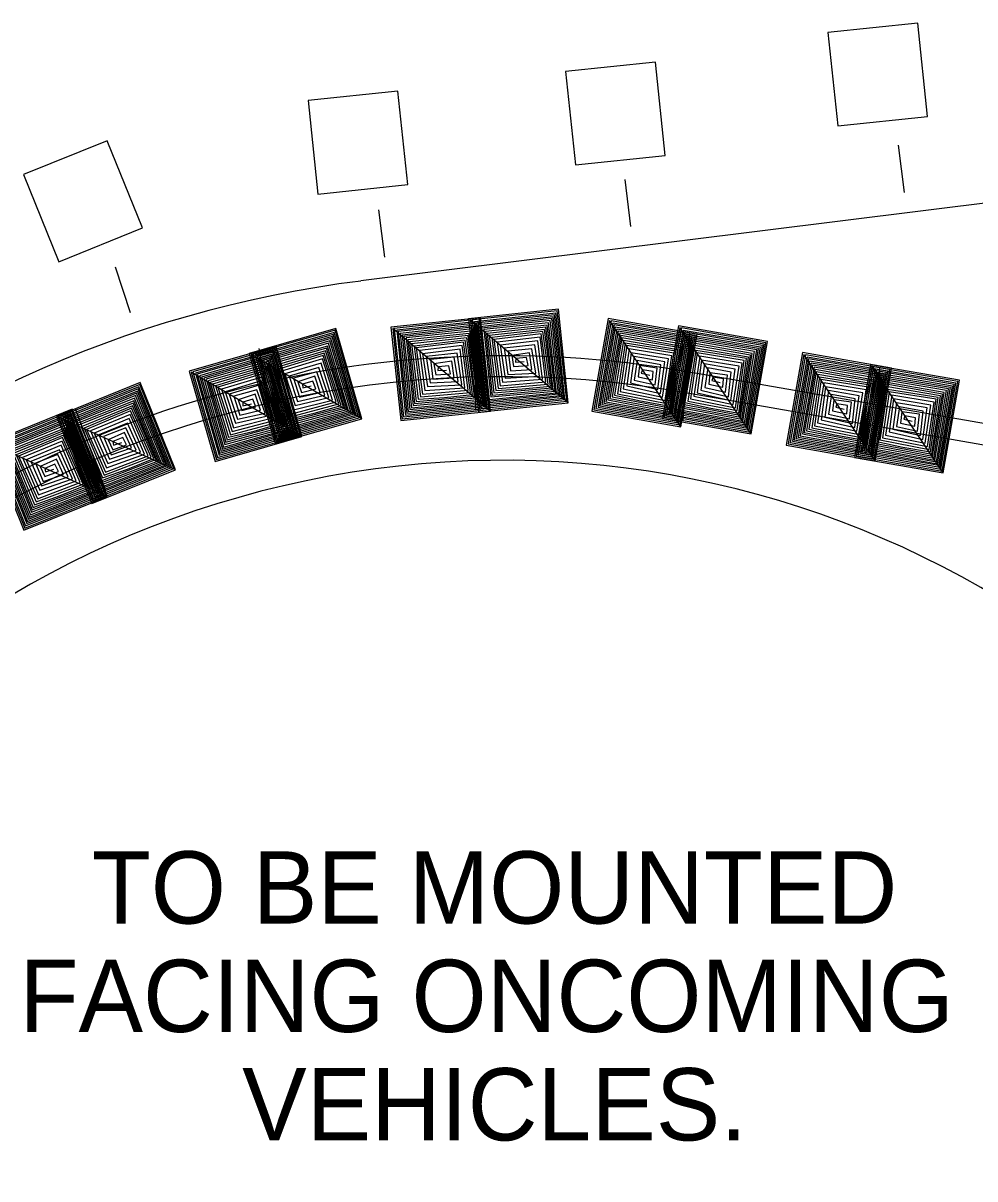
# Model space of a CAD drawing. Extents: x 640253 to 641999, y 298458 to 299646.
# Drawn here: x 641521.2 to 641560.7, y 299475.25 to 299523.22 of the extents above; entities that cross this region are included whole.
import ezdxf

# ---------------------------------------------------------------- set-up
doc = ezdxf.new("R2010")
doc.units = 0
doc.layers.add('2', color=7, linetype='Continuous')

msp = doc.modelspace()

# ---------------------------------------------------------------- linework, layer by layer
at = {"layer": '2'}
for p, q in [((641581.99, 299518.351), (641535.213, 299512.52)), ((641557.777, 299516.199), (641557.534, 299518.16)), ((641546.425, 299514.776), (641546.181, 299516.737)), ((641536.202, 299513.51), (641535.959, 299515.47)), ((641525.648, 299511.199), (641525.023, 299513.093)), ((641539.986, 299507.156), (641539.95, 299510.785)), ((641548.596, 299506.739), (641548.873, 299510.368)), ((641531.654, 299506.149), (641530.994, 299509.724)), ((641590.633, 299501.412), (641548.769, 299508.754)), ((641556.179, 299505.351), (641556.771, 299508.943)), ((641540.211, 299508.545), (641540.211, 299508.545)), ((641548.613, 299507.904), (641548.613, 299507.904)), ((641590.477, 299500.543), (641548.613, 299507.885)), ((641524.625, 299503.806), (641523.375, 299507.208)), ((641531.863, 299507.556), (641531.863, 299507.556)), ((641523.861, 299504.97), (641523.861, 299504.97))]:
    msp.add_line(p, q, dxfattribs=at)
for points in [[(641558.736, 299519.349), (641558.325, 299523.224), (641554.598, 299522.833), (641555.008, 299518.956)], [(641547.846, 299517.735), (641547.436, 299521.61), (641543.709, 299521.218), (641544.119, 299517.341)], [(641537.159, 299516.524), (641536.748, 299520.399), (641533.021, 299520.008), (641533.431, 299516.131)], [(641526.148, 299514.722), (641524.688, 299518.335), (641521.213, 299516.935), (641522.671, 299513.32)]]:
    msp.add_lwpolyline(points, close=True, dxfattribs=at)
for points in [[(641543.819, 299507.468), (641543.41, 299511.347), (641539.686, 299510.951), (641540.096, 299507.074), (641543.819, 299507.468), (641539.758, 299510.897), (641540.156, 299507.147), (641543.765, 299507.528), (641543.367, 299511.278), (641539.827, 299510.903), (641540.213, 299507.228), (641543.686, 299507.595), (641543.306, 299511.191), (641539.925, 299510.828), (641540.296, 299507.305), (641543.621, 299507.658), (641543.256, 299511.12), (641539.99, 299510.774), (641540.348, 299507.383), (641543.554, 299507.72), (641543.198, 299511.037), (641540.067, 299510.695), (641540.409, 299507.458), (641543.492, 299507.772), (641543.135, 299510.962), (641540.15, 299510.624), (641540.475, 299507.533), (641543.419, 299507.833), (641543.075, 299510.884), (641540.225, 299510.564), (641540.538, 299507.607), (641543.334, 299507.884), (641543.006, 299510.789), (641540.321, 299510.505), (641540.606, 299507.705), (641543.277, 299507.947), (641542.94, 299510.685), (641540.39, 299510.422), (641540.667, 299507.787), (641543.202, 299508.016), (641542.89, 299510.601), (641540.454, 299510.345), (641540.733, 299507.872), (641543.154, 299508.091), (641542.831, 299510.505), (641540.544, 299510.255), (641540.815, 299507.97), (641541.913, 299508.037), (641543.079, 299508.16), (641542.763, 299510.42), (641540.65, 299510.168), (641540.913, 299508.06), (641542.994, 299508.239), (641542.702, 299510.326), (641540.736, 299510.089), (641540.998, 299508.174), (641542.894, 299508.337), (641542.65, 299510.193), (641540.875, 299509.985), (641541.092, 299508.322), (641542.756, 299508.441), (641542.559, 299510.037), (641540.996, 299509.851), (641541.198, 299508.489), (641542.625, 299508.566), (641542.625, 299508.572), (641542.436, 299509.876), (641541.156, 299509.732), (641541.313, 299508.639), (641542.481, 299508.693), (641542.315, 299509.708), (641541.327, 299509.612), (641541.431, 299508.791), (641542.311, 299508.845), (641542.209, 299509.539), (641541.473, 299509.432), (641541.55, 299508.972), (641542.154, 299509.014), (641542.088, 299509.351), (641541.644, 299509.303), (641541.631, 299509.155), (641541.99, 299509.172)], [(641535.251, 299506.805), (641534.174, 299510.553), (641530.576, 299509.517), (641531.653, 299505.769), (641535.251, 299506.805), (641530.655, 299509.476), (641531.699, 299505.853), (641535.187, 299506.855), (641534.143, 299510.478), (641530.722, 299509.494), (641531.741, 299505.942), (641535.097, 299506.907), (641534.099, 299510.382), (641530.832, 299509.438), (641531.809, 299506.032), (641535.022, 299506.957), (641534.062, 299510.303), (641530.905, 299509.394), (641531.847, 299506.117), (641534.947, 299507.007), (641534.02, 299510.211), (641530.995, 299509.33), (641531.893, 299506.203), (641534.876, 299507.046), (641533.97, 299510.126), (641531.089, 299509.275), (641531.947, 299506.288), (641534.793, 299507.094), (641533.924, 299510.04), (641531.174, 299509.23), (641531.995, 299506.371), (641534.701, 299507.13), (641533.874, 299509.934), (641531.278, 299509.188), (641532.045, 299506.48), (641534.635, 299507.182), (641533.826, 299509.819), (641531.36, 299509.117), (641532.091, 299506.571), (641534.549, 299507.236), (641533.791, 299509.728), (641531.437, 299509.053), (641532.143, 299506.667), (641534.489, 299507.303), (641533.751, 299509.623), (641531.541, 299508.98), (641532.205, 299506.778), (641533.274, 299507.034), (641534.401, 299507.357), (641533.697, 299509.528), (641531.662, 299508.913), (641532.287, 299506.882), (641534.303, 299507.419), (641533.655, 299509.426), (641531.76, 299508.851), (641532.349, 299507.009), (641534.189, 299507.498), (641533.626, 299509.284), (641531.914, 299508.771), (641532.416, 299507.171), (641534.035, 299507.578), (641533.564, 299509.115), (641532.057, 299508.661), (641532.493, 299507.355), (641533.885, 299507.678), (641533.882, 299507.684), (641533.47, 299508.936), (641532.235, 299508.571), (641532.578, 299507.521), (641533.72, 299507.778), (641533.38, 299508.748), (641532.424, 299508.482), (641532.67, 299507.692), (641533.526, 299507.898), (641533.305, 299508.563), (641532.599, 299508.332), (641532.755, 299507.892), (641533.343, 299508.038), (641533.218, 299508.359), (641532.791, 299508.234), (641532.803, 299508.086), (641533.153, 299508.165)], [(641540.594, 299507.118), (641540.186, 299510.997), (641536.461, 299510.601), (641536.871, 299506.724), (641540.594, 299507.118), (641536.534, 299510.547), (641536.931, 299506.797), (641540.54, 299507.179), (641540.142, 299510.929), (641536.602, 299510.554), (641536.988, 299506.879), (641540.461, 299507.245), (641540.081, 299510.841), (641536.7, 299510.479), (641537.071, 299506.956), (641540.396, 299507.308), (641540.031, 299510.77), (641536.765, 299510.424), (641537.123, 299507.033), (641540.329, 299507.37), (641539.973, 299510.687), (641536.842, 299510.345), (641537.184, 299507.108), (641540.267, 299507.422), (641539.91, 299510.612), (641536.925, 299510.274), (641537.25, 299507.183), (641540.194, 299507.483), (641539.85, 299510.535), (641537, 299510.214), (641537.313, 299507.258), (641540.108, 299507.535), (641539.781, 299510.439), (641537.096, 299510.156), (641537.381, 299507.356), (641540.052, 299507.597), (641539.715, 299510.335), (641537.165, 299510.072), (641537.442, 299507.437), (641539.977, 299507.666), (641539.665, 299510.252), (641537.229, 299509.995), (641537.508, 299507.522), (641539.929, 299507.741), (641539.606, 299510.156), (641537.319, 299509.906), (641537.59, 299507.62), (641538.688, 299507.687), (641539.854, 299507.81), (641539.538, 299510.07), (641537.425, 299509.818), (641537.688, 299507.71), (641539.769, 299507.889), (641539.477, 299509.976), (641537.51, 299509.739), (641537.773, 299507.824), (641539.669, 299507.987), (641539.425, 299509.843), (641537.65, 299509.635), (641537.867, 299507.972), (641539.531, 299508.091), (641539.334, 299509.687), (641537.771, 299509.502), (641537.973, 299508.139), (641539.4, 299508.216), (641539.4, 299508.222), (641539.211, 299509.526), (641537.931, 299509.383), (641538.088, 299508.289), (641539.256, 299508.343), (641539.09, 299509.358), (641538.102, 299509.262), (641538.206, 299508.441), (641539.086, 299508.495), (641538.983, 299509.189), (641538.248, 299509.083), (641538.325, 299508.622), (641538.929, 299508.664), (641538.863, 299509.002), (641538.419, 299508.954), (641538.406, 299508.806), (641538.765, 299508.822)], [(641548.496, 299506.472), (641549.167, 299510.314), (641545.477, 299510.958), (641544.806, 299507.116), (641548.496, 299506.472), (641545.534, 299510.885), (641544.885, 299507.17), (641548.459, 299506.545), (641549.106, 299510.26), (641545.6, 299510.872), (641544.963, 299507.233), (641548.402, 299506.631), (641549.025, 299510.193), (641545.673, 299510.772), (641545.063, 299507.285), (641548.356, 299506.71), (641548.956, 299510.139), (641545.721, 299510.704), (641545.133, 299507.343), (641548.311, 299506.787), (641548.877, 299510.074), (641545.773, 299510.606), (641545.213, 299507.399), (641548.265, 299506.854), (641548.798, 299510.018), (641545.834, 299510.516), (641545.298, 299507.454), (641548.211, 299506.933), (641548.719, 299509.962), (641545.89, 299510.437), (641545.377, 299507.508), (641548.142, 299507.006), (641548.625, 299509.889), (641545.967, 299510.354), (641545.471, 299507.583), (641548.106, 299507.081), (641548.534, 299509.806), (641546.008, 299510.256), (641545.552, 299507.645), (641548.052, 299507.168), (641548.463, 299509.741), (641546.05, 299510.162), (641545.64, 299507.708), (641548.027, 299507.254), (641548.379, 299509.664), (641546.111, 299510.052), (641545.744, 299507.781), (641546.819, 299507.543), (641547.973, 299507.341), (641548.29, 299509.601), (641546.19, 299509.939), (641545.863, 299507.839), (641547.913, 299507.441), (641548.206, 299509.526), (641546.25, 299509.839), (641545.977, 299507.927), (641547.844, 299507.562), (641548.119, 299509.414), (641546.356, 299509.702), (641546.106, 299508.043), (641547.74, 299507.699), (641547.988, 299509.289), (641546.436, 299509.539), (641546.256, 299508.174), (641547.648, 299507.856), (641547.65, 299507.862), (641547.827, 299509.168), (641546.556, 299509.381), (641546.406, 299508.287), (641547.546, 299508.018), (641547.665, 299509.039), (641546.688, 299509.218), (641546.563, 299508.399), (641547.423, 299508.21), (641547.515, 299508.906), (641546.779, 299509.006), (641546.727, 299508.541), (641547.319, 299508.416), (641547.348, 299508.758), (641546.909, 299508.835), (641546.854, 299508.695), (641547.204, 299508.614)], [(641551.419, 299506.17), (641552.09, 299510.012), (641548.4, 299510.656), (641547.729, 299506.814), (641551.419, 299506.17), (641548.456, 299510.583), (641547.809, 299506.868), (641551.381, 299506.243), (641552.029, 299509.958), (641548.523, 299510.57), (641547.885, 299506.931), (641551.325, 299506.329), (641551.948, 299509.891), (641548.596, 299510.47), (641547.986, 299506.983), (641551.279, 299506.408), (641551.879, 299509.837), (641548.644, 299510.401), (641548.056, 299507.041), (641551.233, 299506.485), (641551.8, 299509.772), (641548.696, 299510.304), (641548.135, 299507.097), (641551.188, 299506.552), (641551.721, 299509.716), (641548.756, 299510.214), (641548.221, 299507.151), (641551.133, 299506.631), (641551.642, 299509.66), (641548.813, 299510.135), (641548.3, 299507.206), (641551.065, 299506.704), (641551.548, 299509.587), (641548.89, 299510.052), (641548.394, 299507.281), (641551.029, 299506.779), (641551.456, 299509.504), (641548.931, 299509.954), (641548.475, 299507.343), (641550.975, 299506.866), (641551.385, 299509.439), (641548.973, 299509.86), (641548.563, 299507.406), (641550.95, 299506.952), (641551.302, 299509.362), (641549.034, 299509.749), (641548.667, 299507.479), (641549.742, 299507.241), (641550.896, 299507.039), (641551.213, 299509.299), (641549.113, 299509.637), (641548.785, 299507.537), (641550.836, 299507.139), (641551.129, 299509.224), (641549.173, 299509.537), (641548.9, 299507.624), (641550.767, 299507.26), (641551.042, 299509.112), (641549.279, 299509.399), (641549.029, 299507.741), (641550.663, 299507.397), (641550.91, 299508.987), (641549.358, 299509.237), (641549.179, 299507.872), (641550.571, 299507.554), (641550.573, 299507.56), (641550.75, 299508.866), (641549.479, 299509.079), (641549.329, 299507.985), (641550.469, 299507.716), (641550.588, 299508.737), (641549.611, 299508.916), (641549.486, 299508.097), (641550.346, 299507.908), (641550.438, 299508.604), (641549.702, 299508.704), (641549.65, 299508.239), (641550.242, 299508.114), (641550.271, 299508.456), (641549.831, 299508.533), (641549.777, 299508.393), (641550.127, 299508.312)], [(641532.769, 299506.062), (641531.692, 299509.81), (641528.094, 299508.774), (641529.171, 299505.026), (641532.769, 299506.062), (641528.173, 299508.733), (641529.217, 299505.11), (641532.704, 299506.112), (641531.66, 299509.735), (641528.24, 299508.752), (641529.258, 299505.199), (641532.615, 299506.164), (641531.617, 299509.639), (641528.35, 299508.695), (641529.327, 299505.289), (641532.54, 299506.214), (641531.579, 299509.56), (641528.423, 299508.651), (641529.365, 299505.374), (641532.465, 299506.264), (641531.538, 299509.468), (641528.513, 299508.587), (641529.41, 299505.46), (641532.394, 299506.304), (641531.488, 299509.383), (641528.606, 299508.533), (641529.465, 299505.545), (641532.311, 299506.351), (641531.442, 299509.297), (641528.692, 299508.487), (641529.513, 299505.629), (641532.219, 299506.387), (641531.392, 299509.191), (641528.796, 299508.445), (641529.563, 299505.737), (641532.152, 299506.439), (641531.344, 299509.077), (641528.877, 299508.374), (641529.608, 299505.829), (641532.067, 299506.493), (641531.309, 299508.985), (641528.954, 299508.31), (641529.66, 299505.924), (641532.006, 299506.56), (641531.269, 299508.881), (641529.059, 299508.237), (641529.723, 299506.035), (641530.792, 299506.291), (641531.919, 299506.614), (641531.215, 299508.785), (641529.179, 299508.17), (641529.804, 299506.139), (641531.821, 299506.677), (641531.173, 299508.683), (641529.277, 299508.108), (641529.867, 299506.266), (641531.706, 299506.756), (641531.144, 299508.541), (641529.431, 299508.029), (641529.934, 299506.429), (641531.552, 299506.835), (641531.081, 299508.372), (641529.575, 299507.918), (641530.01, 299506.612), (641531.402, 299506.935), (641531.4, 299506.941), (641530.988, 299508.193), (641529.752, 299507.829), (641530.096, 299506.779), (641531.238, 299507.035), (641530.898, 299508.006), (641529.942, 299507.739), (641530.188, 299506.949), (641531.044, 299507.156), (641530.823, 299507.82), (641530.117, 299507.589), (641530.273, 299507.149), (641530.861, 299507.295), (641530.736, 299507.616), (641530.309, 299507.491), (641530.321, 299507.343), (641530.671, 299507.422)], [(641556.563, 299505.06), (641557.233, 299508.901), (641553.544, 299509.545), (641552.873, 299505.704), (641556.563, 299505.06), (641553.6, 299509.472), (641552.952, 299505.758), (641556.525, 299505.133), (641557.173, 299508.847), (641553.667, 299509.46), (641553.029, 299505.82), (641556.469, 299505.218), (641557.092, 299508.781), (641553.74, 299509.36), (641553.129, 299505.872), (641556.423, 299505.297), (641557.023, 299508.726), (641553.788, 299509.291), (641553.2, 299505.931), (641556.377, 299505.374), (641556.944, 299508.662), (641553.84, 299509.193), (641553.279, 299505.987), (641556.331, 299505.441), (641556.865, 299508.606), (641553.9, 299509.104), (641553.365, 299506.041), (641556.277, 299505.52), (641556.785, 299508.549), (641553.956, 299509.024), (641553.444, 299506.095), (641556.209, 299505.593), (641556.692, 299508.476), (641554.034, 299508.941), (641553.538, 299506.17), (641556.173, 299505.668), (641556.6, 299508.393), (641554.075, 299508.843), (641553.619, 299506.233), (641556.119, 299505.756), (641556.529, 299508.329), (641554.117, 299508.749), (641553.706, 299506.295), (641556.094, 299505.841), (641556.446, 299508.252), (641554.177, 299508.639), (641553.811, 299506.368), (641554.885, 299506.131), (641556.04, 299505.929), (641556.356, 299508.189), (641554.256, 299508.526), (641553.929, 299506.427), (641555.979, 299506.029), (641556.273, 299508.114), (641554.317, 299508.427), (641554.044, 299506.514), (641555.91, 299506.149), (641556.186, 299508.002), (641554.423, 299508.289), (641554.173, 299506.631), (641555.806, 299506.287), (641556.054, 299507.877), (641554.502, 299508.127), (641554.323, 299506.762), (641555.715, 299506.443), (641555.717, 299506.449), (641555.894, 299507.756), (641554.623, 299507.968), (641554.473, 299506.874), (641555.613, 299506.606), (641555.731, 299507.627), (641554.754, 299507.806), (641554.629, 299506.987), (641555.49, 299506.797), (641555.581, 299507.493), (641554.846, 299507.593), (641554.794, 299507.129), (641555.385, 299507.004), (641555.415, 299507.345), (641554.975, 299507.422), (641554.921, 299507.283), (641555.271, 299507.202)], [(641559.385, 299504.556), (641560.056, 299508.397), (641556.367, 299509.041), (641555.696, 299505.199), (641559.385, 299504.556), (641556.423, 299508.968), (641555.775, 299505.254), (641559.348, 299504.629), (641559.996, 299508.343), (641556.49, 299508.956), (641555.852, 299505.316), (641559.292, 299504.714), (641559.915, 299508.276), (641556.563, 299508.856), (641555.952, 299505.368), (641559.246, 299504.793), (641559.846, 299508.222), (641556.611, 299508.787), (641556.023, 299505.427), (641559.2, 299504.87), (641559.767, 299508.158), (641556.663, 299508.689), (641556.102, 299505.483), (641559.154, 299504.937), (641559.688, 299508.101), (641556.723, 299508.599), (641556.188, 299505.537), (641559.1, 299505.016), (641559.608, 299508.045), (641556.779, 299508.52), (641556.267, 299505.591), (641559.031, 299505.089), (641559.515, 299507.972), (641556.856, 299508.437), (641556.361, 299505.666), (641558.996, 299505.164), (641559.423, 299507.889), (641556.898, 299508.339), (641556.442, 299505.729), (641558.942, 299505.252), (641559.352, 299507.824), (641556.94, 299508.245), (641556.529, 299505.791), (641558.917, 299505.337), (641559.269, 299507.747), (641557, 299508.135), (641556.633, 299505.864), (641557.709, 299505.627), (641558.863, 299505.424), (641559.179, 299507.685), (641557.079, 299508.022), (641556.752, 299505.922), (641558.802, 299505.524), (641559.096, 299507.61), (641557.14, 299507.922), (641556.867, 299506.01), (641558.733, 299505.645), (641559.008, 299507.497), (641557.246, 299507.785), (641556.996, 299506.127), (641558.629, 299505.783), (641558.877, 299507.372), (641557.325, 299507.622), (641557.146, 299506.258), (641558.538, 299505.939), (641558.54, 299505.945), (641558.717, 299507.252), (641557.446, 299507.464), (641557.296, 299506.37), (641558.436, 299506.101), (641558.554, 299507.122), (641557.577, 299507.302), (641557.452, 299506.483), (641558.313, 299506.293), (641558.404, 299506.989), (641557.669, 299507.089), (641557.617, 299506.624), (641558.209, 299506.499), (641558.238, 299506.841), (641557.798, 299506.918), (641557.744, 299506.779), (641558.094, 299506.697)], [(641527.517, 299504.687), (641526.059, 299508.304), (641522.586, 299506.901), (641524.044, 299503.285), (641527.517, 299504.687), (641522.669, 299506.868), (641524.084, 299503.372), (641527.448, 299504.731), (641526.035, 299508.226), (641522.733, 299506.893), (641524.115, 299503.466), (641527.352, 299504.772), (641526, 299508.127), (641522.848, 299506.847), (641524.173, 299503.562), (641527.273, 299504.814), (641525.973, 299508.043), (641522.925, 299506.814), (641524.202, 299503.651), (641527.192, 299504.856), (641525.94, 299507.947), (641523.021, 299506.76), (641524.24, 299503.739), (641527.119, 299504.889), (641525.9, 299507.858), (641523.121, 299506.714), (641524.284, 299503.831), (641527.031, 299504.927), (641525.863, 299507.768), (641523.211, 299506.677), (641524.323, 299503.92), (641526.936, 299504.954), (641525.823, 299507.656), (641523.319, 299506.647), (641524.363, 299504.033), (641526.863, 299504.999), (641525.788, 299507.539), (641523.406, 299506.585), (641524.398, 299504.127), (641526.773, 299505.043), (641525.763, 299507.443), (641523.49, 299506.529), (641524.438, 299504.229), (641526.706, 299505.104), (641525.731, 299507.337), (641523.602, 299506.468), (641524.49, 299504.343), (641525.527, 299504.71), (641526.615, 299505.149), (641525.69, 299507.235), (641523.727, 299506.412), (641524.559, 299504.458), (641526.51, 299505.202), (641525.656, 299507.129), (641523.831, 299506.36), (641524.611, 299504.591), (641526.388, 299505.268), (641525.644, 299506.985), (641523.994, 299506.297), (641524.659, 299504.76), (641526.227, 299505.331), (641525.598, 299506.81), (641524.148, 299506.204), (641524.715, 299504.947), (641526.067, 299505.414), (641526.065, 299505.42), (641525.525, 299506.622), (641524.334, 299506.133), (641524.785, 299505.124), (641525.894, 299505.497), (641525.454, 299506.427), (641524.531, 299506.064), (641524.856, 299505.304), (641525.688, 299505.597), (641525.398, 299506.235), (641524.721, 299505.931), (641524.921, 299505.51), (641525.492, 299505.716), (641525.334, 299506.022), (641524.921, 299505.854), (641524.95, 299505.708), (641525.29, 299505.822)], [(641524.694, 299503.577), (641523.236, 299507.193), (641519.763, 299505.791), (641521.221, 299502.174), (641524.694, 299503.577), (641519.846, 299505.758), (641521.26, 299502.262), (641524.625, 299503.62), (641523.213, 299507.116), (641519.91, 299505.783), (641521.292, 299502.356), (641524.529, 299503.662), (641523.177, 299507.016), (641520.025, 299505.737), (641521.35, 299502.452), (641524.45, 299503.704), (641523.15, 299506.933), (641520.102, 299505.704), (641521.379, 299502.541), (641524.369, 299503.745), (641523.117, 299506.837), (641520.198, 299505.649), (641521.417, 299502.629), (641524.296, 299503.779), (641523.077, 299506.747), (641520.298, 299505.604), (641521.461, 299502.72), (641524.209, 299503.816), (641523.04, 299506.658), (641520.388, 299505.566), (641521.5, 299502.81), (641524.113, 299503.843), (641523, 299506.545), (641520.496, 299505.537), (641521.54, 299502.922), (641524.04, 299503.889), (641522.965, 299506.429), (641520.584, 299505.474), (641521.575, 299503.016), (641523.95, 299503.933), (641522.94, 299506.333), (641520.667, 299505.418), (641521.615, 299503.118), (641523.883, 299503.993), (641522.909, 299506.226), (641520.779, 299505.358), (641521.667, 299503.233), (641522.704, 299503.599), (641523.792, 299504.039), (641522.867, 299506.124), (641520.904, 299505.302), (641521.736, 299503.347), (641523.688, 299504.091), (641522.834, 299506.018), (641521.008, 299505.249), (641521.788, 299503.481), (641523.565, 299504.158), (641522.821, 299505.874), (641521.171, 299505.187), (641521.836, 299503.649), (641523.404, 299504.22), (641522.775, 299505.699), (641521.325, 299505.093), (641521.892, 299503.837), (641523.244, 299504.304), (641523.242, 299504.31), (641522.702, 299505.512), (641521.51, 299505.022), (641521.963, 299504.014), (641523.071, 299504.387), (641522.631, 299505.316), (641521.709, 299504.954), (641522.034, 299504.193), (641522.865, 299504.487), (641522.575, 299505.124), (641521.898, 299504.82), (641522.098, 299504.399), (641522.669, 299504.606), (641522.51, 299504.912), (641522.098, 299504.743), (641522.127, 299504.597), (641522.467, 299504.712)]]:
    msp.add_lwpolyline(points, dxfattribs=at)
for radius, start, end in [(47.733, 97.1018, 132.2976), (44.262, 80.0428, 132.2178), (43.393, 80.0478, 246.9218), (39.921, 13.5395, 270)]:
    msp.add_arc((641541.114, 299465.152), radius, start, end, dxfattribs=at)

# ---------------------------------------------------------------- texts
for s, p in [('TO BE MOUNTED', (641524.046, 299485.846)), ('FACING ONCOMING', (641521.046, 299481.346)), (' VEHICLES.', (641529.172, 299476.846))]:
    msp.add_text(s, height=3, dxfattribs=at).set_placement(p)

doc.saveas('drawing.dxf')
